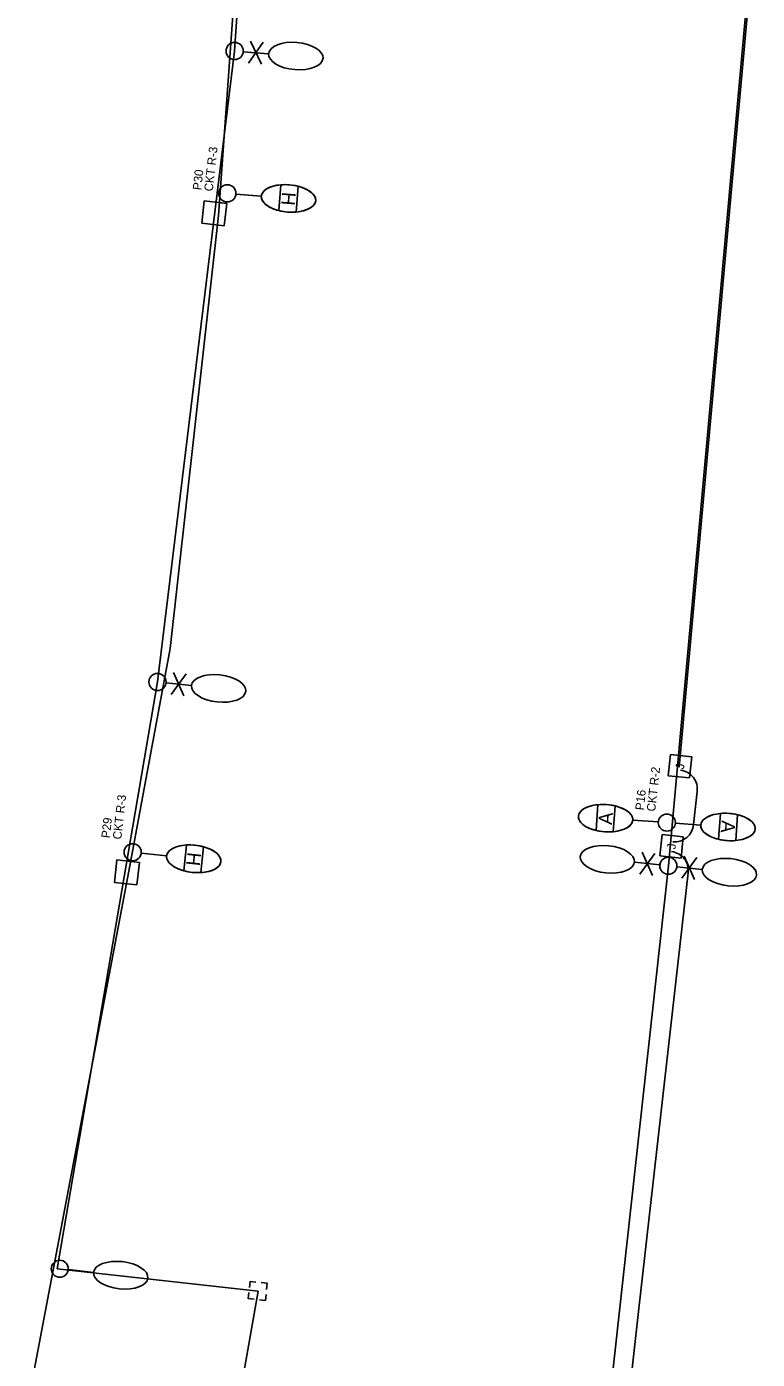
# Model space of a CAD drawing. Extents: x 925407 to 931638, y 609358 to 637063.
# Drawn here: x 931055.6 to 931267.7, y 624341 to 624727.9 of the extents above; entities that cross this region are included whole.
import ezdxf

# ---------------------------------------------------------------- set-up
doc = ezdxf.new("R2010")
doc.units = 0
for name, color, linetype in [('ActivePointCell_dp', 7, 'Continuous'), ('Conduit', 7, 'Continuous'), ('ConduitBM', 7, 'Continuous'), ('ConduitOT', 7, 'Continuous'), ('JunctBoxA', 7, 'Continuous'), ('LiteCond_ep', 7, 'Continuous'), ('Miscellaneous2', 7, 'Continuous'), ('PoleLight', 7, 'Continuous'), ('PoleLight_ep', 7, 'Continuous'), ('PullBox', 7, 'Continuous'), ('TextLabel', 7, 'Continuous')]:
    doc.layers.add(name, color=color, linetype=linetype)

msp = doc.modelspace()

# ---------------------------------------------------------------- linework, layer by layer
at = {"layer": 'Conduit'}
for p, q in [((931064.4, 624367.3), (931122.74, 624360.83)), ((931122.74, 624360.83), (931086.35, 624151.46))]:
    msp.add_line(p, q, dxfattribs=at)
at = {"layer": 'ConduitBM'}
msp.add_line((931245, 624512.96), (931265.18, 624736.28), dxfattribs=at)
at = {"layer": 'ConduitOT'}
for p, q in [((931111.28, 624673.05), (931122.88, 624837.39)), ((931097.2, 624547.36), (931111.28, 624673.05)), ((931085.24, 624482.71), (931097.2, 624547.36)), ((931249.14, 624496.27), (931250.22, 624505.81)), ((931055.56, 624326.38), (931085.24, 624482.71)), ((931233.29, 624355.78), (931247.58, 624482.24)), ((931219.37, 624229.02), (931233.29, 624355.78))]:
    msp.add_line(p, q, dxfattribs=at)
for centre, start, end in [((931244.77, 624506.54), 352.3329, 83.1001), ((931243.66, 624496.72), 264.8132, 355.292), ((931242.13, 624482.97), 352.3329, 83.1001)]:
    msp.add_arc(centre, 5.5, start, end, dxfattribs=at)
at = {"layer": 'LiteCond_ep'}
for p, q in [((931128.83, 624921.45), (931115.95, 624720.78)), ((931241.87, 624484.29), (931265.35, 624743.15)), ((931115.95, 624720.78), (931093.56, 624537.64)), ((931093.56, 624537.64), (931064.4, 624367.3)), ((931212.31, 624215.79), (931241.87, 624484.29))]:
    msp.add_line(p, q, dxfattribs=at)
at = {"layer": 'Miscellaneous2'}
for p, q in [((931129.39, 624681.95), (931128.77, 624674.46)), ((931133.76, 624674.04), (931134.38, 624681.53)), ((931128.77, 624674.46), (931128.77, 624674.46)), ((931133.76, 624674.04), (931133.76, 624674.04)), ((931221.41, 624502.03), (931220.87, 624494.53)), ((931221.41, 624502.03), (931221.41, 624502.03)), ((931225.86, 624494.17), (931226.4, 624501.67)), ((931226.4, 624501.67), (931226.4, 624501.67)), ((931256.96, 624499.47), (931256.42, 624491.98)), ((931256.96, 624499.47), (931256.96, 624499.47)), ((931261.41, 624491.62), (931261.94, 624499.12)), ((931261.94, 624499.12), (931261.94, 624499.12)), ((931101.98, 624490.32), (931101.18, 624482.85)), ((931106.15, 624482.32), (931106.95, 624489.79)), ((931101.18, 624482.85), (931101.18, 624482.85)), ((931106.15, 624482.32), (931106.15, 624482.32))]:
    msp.add_line(p, q, dxfattribs=at)
for centre, major_axis, start_param, end_param in [((931131.58, 624678), (-7.89, 0.66), 4.391271, 5.033538), ((931131.58, 624678), (-7.89, 0.66), 4.391241, 4.391271), ((931131.58, 624678), (-7.89, 0.66), 1.249648, 1.891946), ((931223.63, 624498.1), (7.9, -0.57), 1.249648, 1.891946), ((931259.18, 624495.55), (7.9, -0.57), 1.249648, 1.891946), ((931223.63, 624498.1), (7.9, -0.57), 4.391241, 4.391271), ((931223.63, 624498.1), (7.9, -0.57), 4.391271, 5.033538), ((931259.18, 624495.55), (7.9, -0.57), 4.391241, 4.391271), ((931259.18, 624495.55), (7.9, -0.57), 4.391271, 5.033538), ((931104.07, 624486.32), (-7.88, 0.84), 4.391271, 5.033538), ((931104.07, 624486.32), (-7.88, 0.84), 4.391241, 4.391271), ((931104.07, 624486.32), (-7.88, 0.84), 1.249648, 1.891946)]:
    msp.add_ellipse(centre, major_axis=major_axis, ratio=0.5, start_param=start_param, end_param=end_param, dxfattribs=at)
at = {"layer": 'PoleLight'}
for p, q in [((931128.77, 624674.46), (931129.39, 624681.95)), ((931134.38, 624681.53), (931133.76, 624674.04)), ((931116.28, 624679.27), (931123.68, 624678.65)), ((931220.87, 624494.53), (931221.41, 624502.03)), ((931226.4, 624501.67), (931225.86, 624494.17)), ((931256.42, 624491.98), (931256.96, 624499.47)), ((931261.94, 624499.12), (931261.41, 624491.62)), ((931238.94, 624497), (931231.53, 624497.53)), ((931243.88, 624496.65), (931251.28, 624496.11)), ((931088.81, 624487.95), (931096.19, 624487.16)), ((931101.18, 624482.85), (931101.98, 624490.32)), ((931106.95, 624489.79), (931106.15, 624482.32))]:
    msp.add_line(p, q, dxfattribs=at)
for centre in [(931113.82, 624679.47), (931113.82, 624679.47), (931241.41, 624496.82), (931241.41, 624496.82), (931086.35, 624488.22), (931086.35, 624488.22)]:
    msp.add_circle(centre, 2.48, dxfattribs=at)
for centre, major_axis in [((931131.58, 624678), (-7.89, 0.66)), ((931223.63, 624498.1), (7.9, -0.57)), ((931259.18, 624495.55), (7.9, -0.57)), ((931104.07, 624486.32), (-7.88, 0.84))]:
    msp.add_ellipse(centre, major_axis=major_axis, ratio=0.5, dxfattribs=at)
for centre, major_axis, start_param, end_param in [((931131.58, 624678), (-7.89, 0.66), 5.033538, 6.283185), ((931131.58, 624678), (-7.89, 0.66), 1.891945, 4.391241), ((931131.58, 624678), (-7.89, 0.66), 0, 0.847605), ((931131.58, 624678), (-7.89, 0.66), 0.847605, 1.249648), ((931223.63, 624498.1), (7.9, -0.57), 1.891945, 4.391241), ((931223.63, 624498.1), (7.9, -0.57), 0.847605, 1.249648), ((931223.63, 624498.1), (7.9, -0.57), 0, 0.847605), ((931259.18, 624495.55), (7.9, -0.57), 1.891945, 4.391241), ((931259.18, 624495.55), (7.9, -0.57), 0.847605, 1.249648), ((931223.63, 624498.1), (7.9, -0.57), 5.033538, 6.283185), ((931259.18, 624495.55), (7.9, -0.57), 0, 0.847605), ((931259.18, 624495.55), (7.9, -0.57), 5.033538, 6.283185), ((931104.07, 624486.32), (-7.88, 0.84), 5.033538, 6.283185), ((931104.07, 624486.32), (-7.88, 0.84), 1.891945, 4.391241), ((931104.07, 624486.32), (-7.88, 0.84), 0, 0.847605), ((931104.07, 624486.32), (-7.88, 0.84), 0.847605, 1.249648)]:
    msp.add_ellipse(centre, major_axis=major_axis, ratio=0.5, start_param=start_param, end_param=end_param, dxfattribs=at)
at = {"layer": 'PoleLight_ep'}
for p, q in [((931123.71, 624716.92), (931120.53, 624723.63)), ((931118.42, 624720.58), (931125.82, 624719.97)), ((931124.23, 624723.33), (931120.01, 624717.22)), ((931101.89, 624539.99), (931097.53, 624533.99)), ((931101.22, 624533.6), (931098.2, 624540.38)), ((931096.02, 624537.38), (931103.4, 624536.6)), ((931233.6, 624481.89), (931237.97, 624487.9)), ((931233.6, 624481.89), (931237.97, 624487.9)), ((931234.27, 624488.29), (931237.29, 624481.5)), ((931234.28, 624488.29), (931237.29, 624481.5)), ((931239.41, 624484.55), (931232.02, 624485.33)), ((931239.4, 624484.55), (931232.02, 624485.33)), ((931244.33, 624484.03), (931251.71, 624483.25)), ((931244.33, 624484.03), (931251.71, 624483.25)), ((931250.13, 624486.69), (931245.76, 624480.69)), ((931250.14, 624486.69), (931245.77, 624480.69)), ((931249.46, 624480.3), (931246.44, 624487.08)), ((931249.45, 624480.3), (931246.44, 624487.08)), ((931067.63, 624367.07), (931075.02, 624366.28))]:
    msp.add_line(p, q, dxfattribs=at)
for centre, radius in [((931115.95, 624720.78), 2.48), ((931093.56, 624537.64), 2.48), ((931241.87, 624484.29), 2.48), ((931241.86, 624484.29), 2.48), ((931065.17, 624367.33), 2.47)]:
    msp.add_circle(centre, radius, dxfattribs=at)
for centre, major_axis in [((931133.71, 624719.32), (7.89, -0.65)), ((931111.28, 624535.77), (7.88, -0.83)), ((931224.15, 624486.17), (-7.88, 0.83)), ((931224.14, 624486.17), (-7.88, 0.83)), ((931259.59, 624482.42), (7.88, -0.83)), ((931259.58, 624482.42), (7.88, -0.83)), ((931082.89, 624365.44), (7.88, -0.84))]:
    msp.add_ellipse(centre, major_axis=major_axis, ratio=0.5, dxfattribs=at)
at = {"layer": 'PullBox'}
for p, q in [((931106.42, 624670.77), (931107.14, 624677.28)), ((931107.14, 624677.28), (931113.65, 624676.56)), ((931113.65, 624676.56), (931112.93, 624670.05)), ((931112.93, 624670.05), (931106.42, 624670.77)), ((931241.82, 624510.43), (931242.48, 624516.59)), ((931242.48, 624516.59), (931248.63, 624515.93)), ((931248.63, 624515.93), (931247.98, 624509.78)), ((931247.98, 624509.78), (931241.82, 624510.43)), ((931239.37, 624487.2), (931240.03, 624493.35)), ((931240.03, 624493.35), (931246.18, 624492.7)), ((931246.18, 624492.7), (931245.53, 624486.54)), ((931081.06, 624479.48), (931081.78, 624485.99)), ((931081.78, 624485.99), (931088.29, 624485.26)), ((931088.29, 624485.26), (931087.57, 624478.75)), ((931245.53, 624486.54), (931239.37, 624487.2)), ((931087.57, 624478.75), (931081.06, 624479.48))]:
    msp.add_line(p, q, dxfattribs=at)
for points in [[(931122.13, 624363.46), (931120.46, 624363.65), (931120.27, 624361.9)], [(931120.1, 624360.41), (931119.91, 624358.68), (931121.58, 624358.5)], [(931125.24, 624361.34), (931125.43, 624363.1), (931123.67, 624363.29)], [(931124.88, 624358.13), (931125.07, 624359.85)], [(931123.12, 624358.33), (931124.88, 624358.13)]]:
    msp.add_lwpolyline(points, dxfattribs=at)

# ---------------------------------------------------------------- texts
at = {"layer": 'ActivePointCell_dp'}
for s, p in [('CKT R-3', (931109.57, 624679.94)), ('P30', (931106.24, 624680.31)), ('CKT R-2', (931238.03, 624499.94)), ('CKT R-3', (931083.03, 624491.85)), ('P16', (931234.7, 624500.31)), ('P29', (931079.7, 624492.22))]:
    msp.add_text(s, height=2.5, rotation=83.6425, dxfattribs=at).set_placement(p)
at = {"layer": 'JunctBoxA'}
for p in [(931246.37, 624512.21), (931243.92, 624488.98)]:
    msp.add_text('J', height=2.48, rotation=83.957, dxfattribs=at).set_placement(p)
at = {"layer": 'TextLabel'}
for s, rotation, p in [('H', 265.2543, (931129.73, 624679.98)), ('A', 85.8928, (931225.5, 624496.1)), ('A', 265.8928, (931257.32, 624497.55)), ('H', 263.8979, (931102.27, 624488.35))]:
    msp.add_text(s, height=4, rotation=rotation, dxfattribs=at).set_placement(p)

doc.saveas('drawing.dxf')
